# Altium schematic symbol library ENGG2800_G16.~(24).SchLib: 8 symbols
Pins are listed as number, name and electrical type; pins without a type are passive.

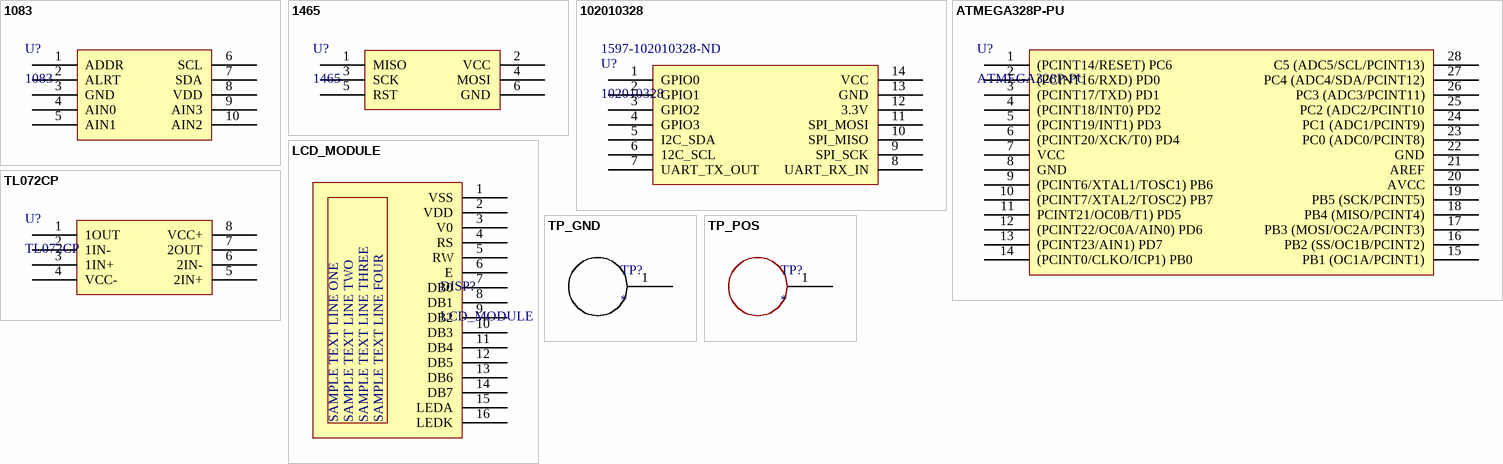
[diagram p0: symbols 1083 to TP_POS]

## 1083
designator U?
EVAL BOARD ADS1115 16-BIT ADC; Manufacturer: Adafruit Industries; Number of Bits: 12; Evaluation Kit: Yes; Number of A/D Converters: 1; Sampling Rate: 3300S/s; Interface: I2C,Serial
pins: 1 ADDR, 2 ALRT, 3 GND, 4 AIN0, 5 AIN1, 6 SCL, 7 SDA, 8 VDD, 9 AIN3, 10 AIN2

## 1465
designator U?
Adafruit 6-pin AVR ISP Breadboard Adapter Mini Kit; Manufacturer: Adafruit Industries
pins: 1 MISO, 2 VCC, 3 SCK, 4 MOSI, 5 RST, 6 GND

## 102010328
designator U?  Supplier Part Number 1: 1597-102010328-ND
Manufacturer: Seeed Studio
pins: 1 GPIO0, 2 GPIO1, 3 GPIO2, 4 GPIO3, 5 I2C_SDA, 6 12C_SCL, 7 UART_TX_OUT, 8 UART_RX_IN, 9 SPI_SCK, 10 SPI_MISO, 11 SPI_MOSI, 12 3.3V, 13 GND, 14 VCC

## ATMEGA328P-PU
designator U?
IC MCU 8BIT 32KB FLASH 28DIP; Manufacturer: Microchip / Atmel; Core Architecture: AVR; RAM Size: 2KB; Number of PWM Channels: 6; Number of Timers/Counters: 3; Min Supply Voltage: 1.8V; Max Supply Voltage: 5.5V; Interface: I2C,SPI,UART,USART,2-Wire; Number of I/Os: 23; Frequency: 20MHz; Oscillator Type: Internal; Data Bus Width: 8b; Number of SPI Channels: 1; Watchdog Timer: Yes; Peripherals: Brown-out Detect/Reset,POR,PWM,WDT
pins: 1 (PCINT14/RESET) PC6, 2 (PCINT16/RXD) PD0, 3 (PCINT17/TXD) PD1, 4 (PCINT18/INT0) PD2, 5 (PCINT19/INT1) PD3, 6 (PCINT20/XCK/T0) PD4, 7 VCC, 8 GND, 9 (PCINT6/XTAL1/TOSC1) PB6, 10 (PCINT7/XTAL2/TOSC2) PB7, 11 PCINT21/OC0B/T1) PD5, 12 (PCINT22/OC0A/AIN0) PD6, 13 (PCINT23/AIN1) PD7, 14 (PCINT0/CLKO/ICP1) PB0, 15 PB1 (OC1A/PCINT1), 16 PB2 (SS/OC1B/PCINT2), 17 PB3 (MOSI/OC2A/PCINT3), 18 PB4 (MISO/PCINT4), 19 PB5 (SCK/PCINT5), 20 AVCC, 21 AREF, 22 GND, 23 PC0 (ADC0/PCINT8), 24 PC1 (ADC1/PCINT9), 25 PC2 (ADC2/PCINT10, 26 PC3 (ADC3/PCINT11), 27 PC4 (ADC4/SDA/PCINT12), 28 C5 (ADC5/SCL/PCINT13)

## LCD_MODULE
designator DISP?
pins: 1 VSS, 2 VDD, 3 V0, 4 RS, 5 RW, 6 E, 7 DB0, 8 DB1, 9 DB2, 10 DB3, 11 DB4, 12 DB5, 13 DB6, 14 DB7, 15 LEDA, 16 LEDK

## TL072CP
designator U?
IC, OP AMP, DUAL JFET, DIP8; Bandwidth:3MHz; No. of Amplifiers:2; Slew Rate:13V/ s; Supply Voltage Range:7V to 36V; Amplifier Case Style:DIP; No. of Pins:8; Operating Temperature Min:0 C; Operating Temperature Max:70 C; ;RoHS Compliant: Yes; Manufacturer: Texas Instruments; Bandwidth: 3MHz; Number of Channels: 2; Voltage Gain: 106.02dB; Nominal Supply Current: 5mA; Max Supply Voltage: 18V; Min Dual Supply Voltage: 3.5V; Dual Supply Voltage: 9V; Common Mode Rejection Ratio: 70dB; Slew Rate: 13V/µs; Max I/O Voltage: 10mV; Input Bias Current: 200pA; Input Offset Voltage (Vos): 3mV; Operating Supply Current: 1.4mA
pins: 1 1OUT, 2 1IN-, 3 1IN+, 4 VCC-, 5 2IN+, 6 2IN-, 7 2OUT, 8 VCC+

## TP_GND
designator TP?
Test Point MultiPurpose THM .445 L .125OD Heat Resistant Nylon 46 Red; Manufacturer: Keystone Electronics; Manufacturer Part Number: 5010; Body Material: Bronze,PBT; Plating: Silver; Number of Ports: 1; Inside Diameter: 1.78mm; Hole Diameter: 1.6mm
pins: 1 5

## TP_POS
designator TP?
Test Point MultiPurpose THM .445 L .125OD Heat Resistant Nylon 46 Red; Manufacturer: Keystone Electronics; Manufacturer Part Number: 5010; Body Material: Bronze,PBT; Plating: Silver; Number of Ports: 1; Inside Diameter: 1.78mm; Hole Diameter: 1.6mm
pins: 1 5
